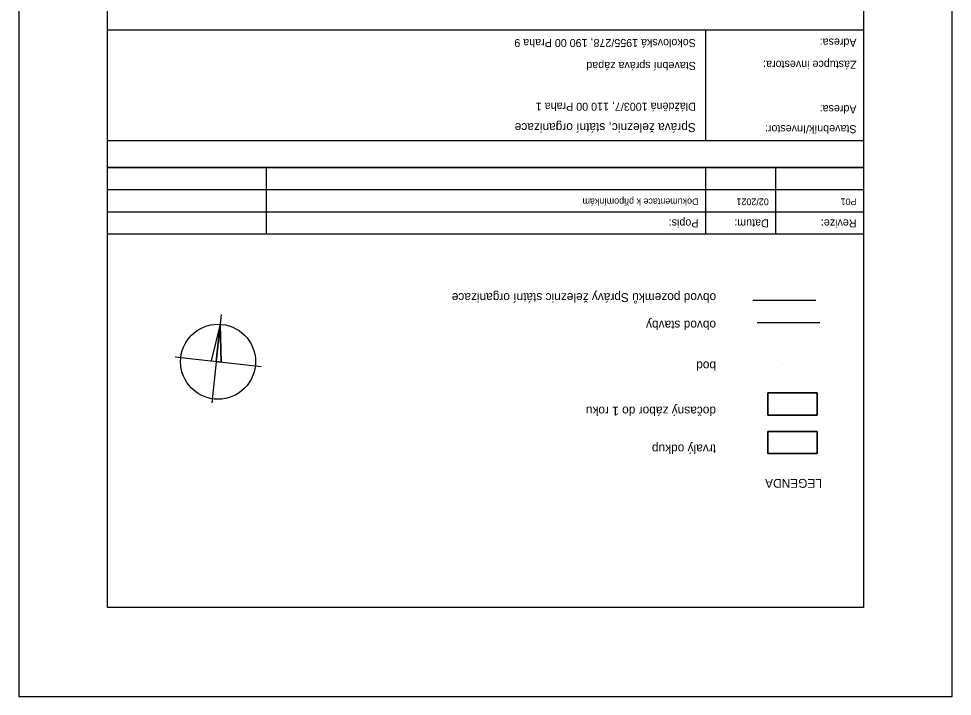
# Model space of a CAD drawing. Extents: x -728472.2 to -728419.7, y -1073099.3 to -1073025.
# Drawn here: x -728472.2 to -728419.7, y -1073099.3 to -1073061.2 of the extents above; entities that cross this region are included whole.
import ezdxf

# ---------------------------------------------------------------- set-up
doc = ezdxf.new("R2010")
doc.units = 0
for name, color, linetype in [('B1_body_poloha', 7, 'Continuous'), ('Dočasný_do_1_roku_maska', 7, 'Continuous'), ('LEGENDA', 7, 'Continuous'), ('Popisky', 7, 'Continuous'), ('Rozpiska_pole_1', 7, 'Continuous'), ('Rozpiska_pole_4', 7, 'Continuous'), ('Rozpiska_pole_5', 7, 'Continuous'), ('Rozpiska_pole_6', 7, 'Continuous'), ('Trvalý_pro_XXX', 7, 'Continuous')]:
    doc.layers.add(name, color=color, linetype=linetype)

msp = doc.modelspace()

# ---------------------------------------------------------------- linework, layer by layer
msp.add_lwpolyline([(-728419.685, -1073025.028), (-728472.185, -1073025.028), (-728472.185, -1073099.278), (-728419.685, -1073099.278)], close=True)
msp.add_lwpolyline([(-728419.685, -1073025.028), (-728472.185, -1073025.028), (-728472.185, -1073099.278), (-728419.685, -1073099.278)], close=True)
at = {"layer": 'B1_body_poloha'}
msp.add_line((-728429.182, -1073080.577), (-728429.182, -1073080.577), dxfattribs=at)
at = {"layer": 'Dočasný_do_1_roku_maska'}
msp.add_lwpolyline([(-728430.068, -1073082.211), (-728430.068, -1073083.453), (-728427.285, -1073083.453), (-728427.285, -1073082.211)], close=True, dxfattribs=at)
at = {"layer": 'LEGENDA'}
for p, q in [((-728427.368, -1073077.012), (-728430.896, -1073077.008)), ((-728427.14, -1073078.262), (-728430.668, -1073078.259))]:
    msp.add_line(p, q, dxfattribs=at)
for points in [[(-728427.285, -1073083.453), (-728430.068, -1073083.453), (-728430.068, -1073082.211), (-728427.285, -1073082.211)], [(-728427.285, -1073085.624), (-728430.068, -1073085.624), (-728430.068, -1073084.381), (-728427.285, -1073084.381)]]:
    msp.add_lwpolyline(points, close=True, dxfattribs=at)
at = {"layer": 'Popisky'}
for p, q in [((-728460.792, -1073077.788), (-728461.323, -1073082.761)), ((-728463.39, -1073080.184), (-728458.556, -1073080.717))]:
    msp.add_line(p, q, dxfattribs=at)
msp.add_lwpolyline([(-728460.797, -1073080.465), (-728460.851, -1073078.339), (-728461.353, -1073080.407)], dxfattribs=at)
for points in [[(-728461.075, -1073080.439), (-728460.796, -1073080.47), (-728460.851, -1073078.339)], [(-728460.796, -1073080.47), (-728461.075, -1073080.439), (-728460.851, -1073078.339)]]:
    msp.add_lwpolyline(points, close=True, dxfattribs=at)
msp.add_circle((-728460.973, -1073080.451), 2.111, dxfattribs=at)
at = {"layer": 'Rozpiska_pole_1'}
msp.add_lwpolyline([(-728424.685, -1073094.278), (-728467.185, -1073094.278), (-728467.185, -1073029.278), (-728424.685, -1073029.278)], close=True, dxfattribs=at)
at = {"layer": 'Rozpiska_pole_4'}
for p, q in [((-728424.685, -1073069.532), (-728467.185, -1073069.532)), ((-728458.26, -1073069.532), (-728458.26, -1073073.282)), ((-728433.572, -1073069.532), (-728433.572, -1073073.282)), ((-728429.622, -1073069.532), (-728429.622, -1073073.282)), ((-728424.685, -1073070.782), (-728467.185, -1073070.782)), ((-728424.685, -1073072.032), (-728467.185, -1073072.032))]:
    msp.add_line(p, q, dxfattribs=at)
msp.add_lwpolyline([(-728424.685, -1073073.282), (-728467.185, -1073073.282), (-728467.185, -1073069.532), (-728424.685, -1073069.532)], close=True, dxfattribs=at)
at = {"layer": 'Rozpiska_pole_5'}
msp.add_line((-728433.572, -1073061.778), (-728433.572, -1073068.028), dxfattribs=at)
msp.add_lwpolyline([(-728424.685, -1073068.028), (-728467.185, -1073068.028), (-728467.185, -1073061.778), (-728424.685, -1073061.778)], close=True, dxfattribs=at)
at = {"layer": 'Trvalý_pro_XXX'}
msp.add_lwpolyline([(-728427.285, -1073084.381), (-728430.068, -1073084.381), (-728430.068, -1073085.624), (-728427.285, -1073085.624)], close=True, dxfattribs=at)

# ---------------------------------------------------------------- texts
at = {"layer": 'LEGENDA'}
for s, p in [('obvod pozemků Správy železnic státní organizace', (-728432.966, -1073076.597)), ('obvod stavby', (-728432.968, -1073078.145)), ('bod ', (-728432.97, -1073080.437)), ('dočasný zábor do 1 roku', (-728432.973, -1073082.979)), ('trvalý odkup', (-728432.973, -1073085.111)), ('LEGENDA', (-728427.017, -1073087.047))]:
    msp.add_text(s, height=0.5, rotation=180, dxfattribs=at).set_placement(p)
at = {"layer": 'Rozpiska_pole_4'}
for s, height, p in [('Dokumentace k připomínkám', 0.375, (-728433.959, -1073071.27)), ('02/2021', 0.375, (-728430.009, -1073071.27)), ('P01', 0.375, (-728425.072, -1073071.27)), ('Popis:', 0.45, (-728433.959, -1073072.445)), ('Datum:', 0.45, (-728430.009, -1073072.445)), ('Revize:', 0.45, (-728425.072, -1073072.445))]:
    msp.add_text(s, height=height, rotation=180, dxfattribs=at).set_placement(p)
at = {"layer": 'Rozpiska_pole_5'}
for s, height, p in [('Adresa:', 0.45, (-728425.072, -1073062.271)), ('Zástupce investora:', 0.45, (-728425.072, -1073063.521)), ('Adresa:', 0.45, (-728425.072, -1073066.021)), ('Správa železnic, státní organizace', 0.5, (-728434.109, -1073067.033)), ('Stavebník/Investor:', 0.45, (-728425.072, -1073067.146))]:
    msp.add_text(s, height=height, rotation=180, dxfattribs=at).set_placement(p)
at = {"layer": 'Rozpiska_pole_6'}
for s, p in [('Sokolovská 1955/278, 190 00 Praha 9', (-728434.109, -1073062.299)), ('Stavební správa západ', (-728434.109, -1073063.587)), ('Dlážděná 1003/7, 110 00 Praha 1', (-728434.109, -1073065.883))]:
    msp.add_text(s, height=0.45, rotation=180, dxfattribs=at).set_placement(p)

doc.saveas('drawing.dxf')
